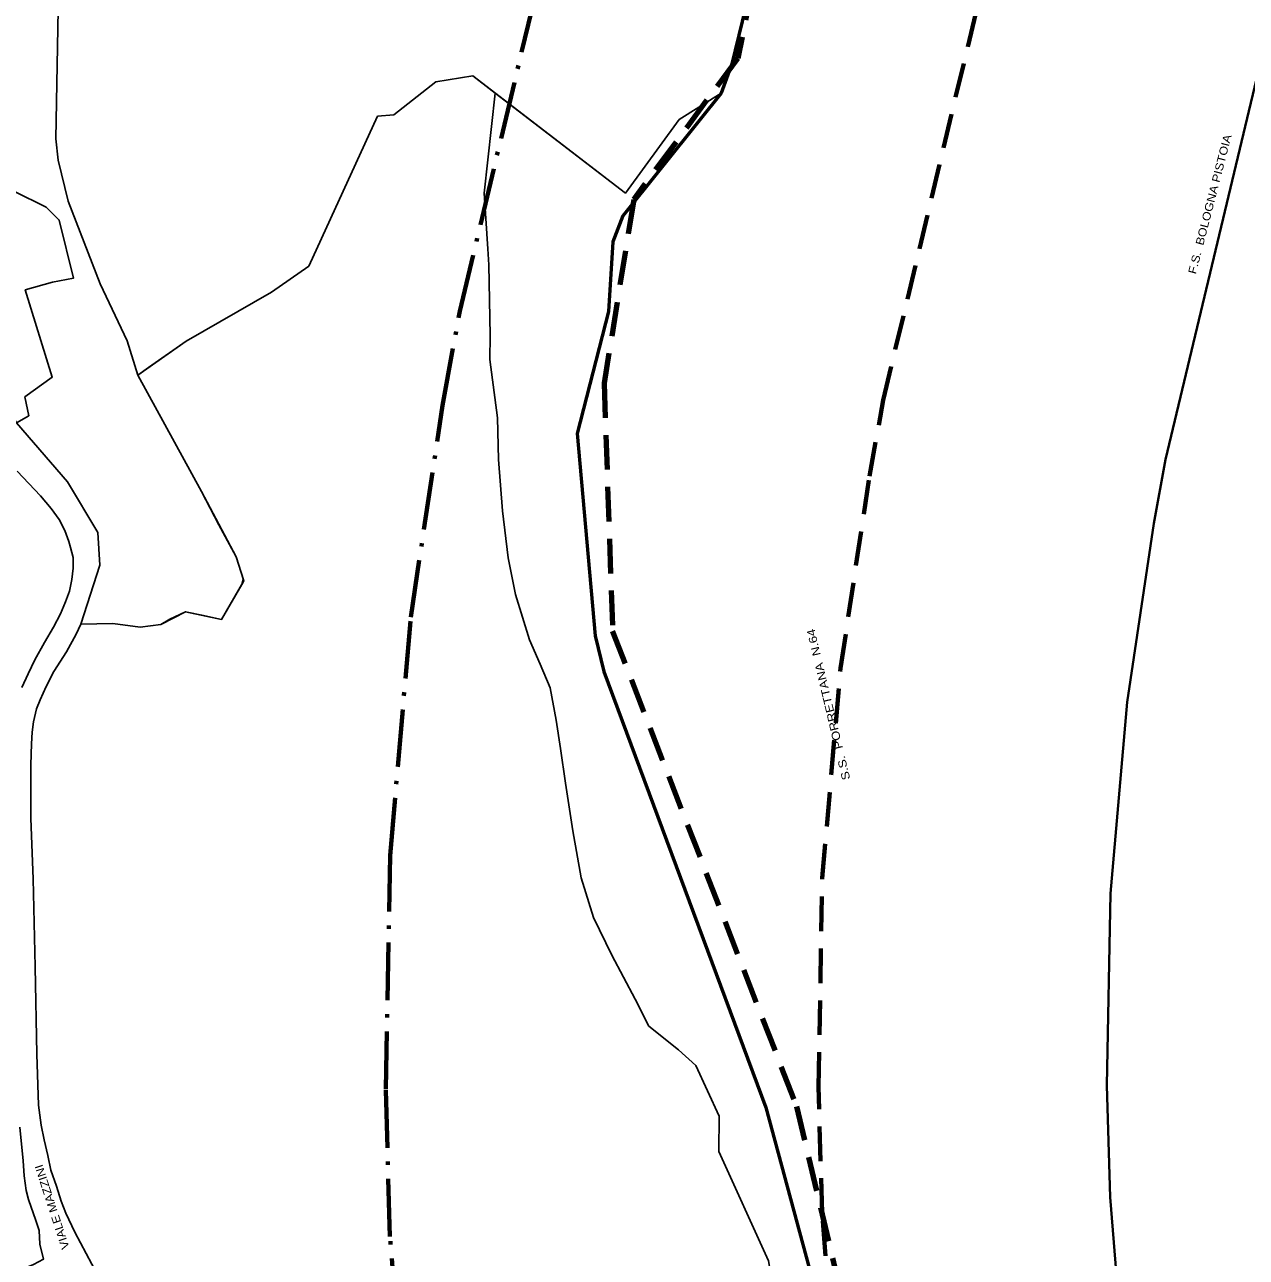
# Model space of a CAD drawing. Extents: x 654952 to 658955, y 890426 to 894481.
# Drawn here: x 657737.9 to 658161.5, y 891916.2 to 892343.7 of the extents above; entities that cross this region are included whole.
import ezdxf

# ---------------------------------------------------------------- set-up
doc = ezdxf.new("R2010")
doc.units = 0
doc.header["$LTSCALE"] = 4
doc.linetypes.add('DOT_DASHED', pattern=[7.7, 5, -1.2, 0.3, -1.2])
doc.linetypes.add('MEDIUM_DASHED', pattern=[4.5, 3, -1.5])
for name, color, linetype, lineweight in [('1', 7, 'Continuous', 25), ('12', 7, 'Continuous', 25), ('26', 7, 'Continuous', 25), ('43', 7, 'Continuous', 25), ('45', 7, 'Continuous', 25), ('55', 7, 'Continuous', 25), ('59', 7, 'Continuous', 53), ('7', 7, 'MEDIUM_DASHED', 100), ('9', 7, 'Continuous', 25)]:
    doc.layers.add(name, color=color, linetype=linetype, lineweight=lineweight)
doc.layers.add('58', color=7, linetype='Continuous')

msp = doc.modelspace()

# ---------------------------------------------------------------- linework, layer by layer
at = {"layer": '1'}
msp.add_lwpolyline([(657736.87, 892113.86), (657739.08, 892118.64), (657741.43, 892123.47), (657744.72, 892129.43), (657747.87, 892134.83), (657750.35, 892139.46), (657752.08, 892143.6), (657753.42, 892147.3), (657754.2, 892151.26), (657754.74, 892155.23), (657754.72, 892158.98), (657753.83, 892162.46), (657753.16, 892164.5), (657751.77, 892168.35), (657749.88, 892172.07), (657747.06, 892175.92), (657743.34, 892180.35), (657735.27, 892188.83)], dxfattribs=at)
at = {"layer": '12'}
for points in [[(657738.45, 891939.43), (657737.71, 891944.48), (657737.33, 891949.76), (657736.18, 891961.41)], [(657742.96, 891925.58), (657741.82, 891928.98), (657739.24, 891936.31), (657738.45, 891939.43)], [(657740.93, 891913.75), (657744.38, 891915.57), (657743.11, 891920.79), (657742.96, 891925.58)]]:
    msp.add_lwpolyline(points, dxfattribs=at)
at = {"layer": '26'}
for points in [[(657897.24, 892285.3), (657901.07, 892319.94), (657893.25, 892325.94), (657880.5, 892323.94), (657865.87, 892312.44), (657860.25, 892311.94), (657836.37, 892259.94), (657823.5, 892250.94), (657793.84, 892234.02), (657777.08, 892222.16)], [(657899.25, 892235.94), (657898.87, 892260.44), (657898.5, 892265.94), (657897.24, 892285.3)], [(657954.34, 891996.44), (657949.62, 892005.77), (657941.44, 892020.98), (657935.11, 892034.15), (657930.83, 892047.81), (657927.92, 892064.19), (657925.38, 892080.66), (657923.63, 892092.72), (657922.23, 892102.53), (657920.15, 892113.8), (657916.61, 892121.94), (657912.97, 892130.41), (657908.08, 892146.1), (657905.52, 892158.87), (657903.61, 892175.14), (657902.18, 892192.88), (657901.88, 892207.4), (657899.22, 892227.63), (657899.25, 892235.94)], [(657777.08, 892222.16), (657799.22, 892181.84), (657805.23, 892170.31), (657811.18, 892159.16), (657813.86, 892150.82), (657806.18, 892137.49)], [(657806.18, 892137.49), (657793.71, 892140.15), (657788.28, 892137.59), (657785.14, 892135.71), (657777.91, 892134.81), (657768.46, 892136), (657757.41, 892135.8)], [(657757.41, 892135.8), (657755.8, 892132.36), (657752.4, 892126.19), (657748.02, 892119.46), (657745.35, 892114.23), (657743.28, 892109.59), (657742.02, 892106.41), (657741, 892101.92), (657740.46, 892098.33), (657740.3, 892094.38), (657740.05, 892087.02), (657739.99, 892082.71), (657740.07, 892068.48), (657740.87, 892047.47), (657741.54, 892017.02), (657742.06, 891986.65), (657742.74, 891969.03)], [(657999.81, 891891.24), (657995.85, 891915.04), (657978.62, 891952.92), (657978.65, 891965.17), (657970.58, 891982.77), (657964.55, 891988.16), (657954.34, 891996.44)], [(657742.74, 891969.03), (657743.62, 891962.05), (657744.69, 891956.96), (657745.87, 891951.55), (657746.96, 891946.43), (657748.9, 891940.97), (657750.54, 891935.67), (657752.22, 891931.58), (657755.25, 891924.94), (657761.15, 891913.87), (657767.14, 891902.38), (657777.05, 891883.31), (657778.51, 891883.96), (657786.61, 891867.17), (657790.42, 891858.02), (657795.5, 891846.02)]]:
    msp.add_lwpolyline(points, dxfattribs=at)
at = {"layer": '43'}
msp.add_line((657813.16, 892149.6), (657813.62, 892151.58), dxfattribs=at)
for points in [[(658040.09, 892492.62), (658015.06, 892461.51), (658007.4, 892428.35), (657983.11, 892330.2), (657979.38, 892319.96), (657964.89, 892310.88), (657946.17, 892285.3), (657893.25, 892325.94), (657880.5, 892323.94), (657865.87, 892312.44), (657860.25, 892311.94), (657836.37, 892259.94), (657823.5, 892250.94), (657793.84, 892234.02), (657780.84, 892224.82)], [(657780.84, 892224.82), (657777.08, 892222.16), (657773.41, 892234.07), (657764.09, 892253.86), (657753.01, 892282.56), (657749.48, 892296.7), (657748.68, 892304.16), (657749.49, 892348.88), (657750.02, 892370.71)], [(657780.84, 892224.82), (657777.08, 892222.16), (657773.41, 892234.07), (657764.09, 892253.86), (657753.01, 892282.56), (657749.48, 892296.7), (657748.68, 892304.16), (657749.49, 892348.88), (657750.02, 892370.71)], [(657703.61, 892356.05), (657701.75, 892325.28), (657700.74, 892305.16), (657700.57, 892296.04), (657702.26, 892286.06), (657704.79, 892275.08), (657714.76, 892245.49), (657723.21, 892226.22), (657735.04, 892205.6), (657752.77, 892185.16), (657763.24, 892167.58), (657763.92, 892156.25), (657757.41, 892135.8), (657768.46, 892136), (657777.91, 892134.81), (657785.14, 892135.71), (657793.71, 892140.15), (657799.95, 892138.82), (657806.18, 892137.49), (657813.16, 892149.6), (657813.62, 892151.58)], [(657979.38, 892319.96), (657964.89, 892310.88), (657946.17, 892285.3), (657901.07, 892319.93), (657897.24, 892285.3)], [(658029.64, 891844.65), (658013.51, 891867.03), (658011.96, 891871.69), (658014.13, 891885.66), (658014.44, 891898.08), (658011.96, 891904.91), (657994.9, 891968.23), (657938.75, 892119.41), (657935.65, 892131.82), (657929.44, 892201.99), (657940.3, 892244.21), (657941.85, 892268.42), (657945.26, 892277.42), (657971.94, 892310.64), (657979.39, 892319.96)], [(657897.24, 892285.3), (657898.5, 892265.94), (657898.87, 892260.44), (657899.25, 892235.94), (657899.22, 892227.63)], [(657899.22, 892227.63), (657901.88, 892207.4), (657902.18, 892192.88), (657903.61, 892175.14), (657905.52, 892158.87), (657908.08, 892146.1), (657912.97, 892130.41)], [(657813.62, 892151.58), (657811.18, 892159.16), (657805.23, 892170.31), (657799.22, 892181.84), (657777.08, 892222.16), (657780.84, 892224.82)], [(657813.62, 892151.58), (657813.86, 892150.82), (657813.16, 892149.6)], [(657912.97, 892130.41), (657916.61, 892121.94), (657920.15, 892113.8), (657922.23, 892102.53), (657923.63, 892092.72), (657925.38, 892080.66), (657927.92, 892064.19), (657930.83, 892047.81), (657935.11, 892034.15), (657941.44, 892020.98), (657949.62, 892005.77), (657954.34, 891996.44), (657964.55, 891988.16), (657970.58, 891982.77), (657978.65, 891965.17), (657978.62, 891952.92), (657995.85, 891915.04), (657999.81, 891891.24)]]:
    msp.add_lwpolyline(points, dxfattribs=at)
at = {"layer": '45', "linetype": 'DOT_DASHED', "lineweight": 70}
msp.add_lwpolyline([(658011.88, 891241.38), (657961.94, 891450.62), (657946.98, 891502.99), (657940.95, 891519.94), (657920.53, 891605.37), (657908.94, 891653.27), (657885.37, 891755.88), (657877.62, 891800.36), (657869.23, 891865.26), (657864.56, 891923.48), (657863.08, 891974.59), (657864.59, 892055.62), (657871.75, 892138.2), (657882.82, 892211.71), (657888.75, 892244.36), (657949.53, 892498.78)], dxfattribs=at)
at = {"layer": '45', "linetype": 'MEDIUM_DASHED', "lineweight": 70}
msp.add_lwpolyline([(658157.77, 891276.21), (658107.08, 891488.64), (658089.9, 891548.82), (658084.95, 891562.68), (658066.38, 891640.44), (658054.95, 891687.7), (658032.46, 891785.55), (658025.97, 891822.86), (658018.45, 891880.89), (658014.38, 891931.66), (658013.11, 891975.37), (658014.47, 892047.73), (658020.79, 892120.53), (658030.81, 892187.14), (658035.6, 892213.52), (658095.39, 892463.77)], dxfattribs=at)
at = {"layer": '45', "lineweight": 40}
msp.add_lwpolyline([(658255.04, 891299.42), (658203.84, 891513.99), (658185.17, 891579.38), (658180.96, 891591.18), (658163.61, 891663.81), (658152.28, 891710.65), (658130.52, 891805.34), (658124.86, 891837.86), (658117.94, 891891.31), (658114.27, 891937.11), (658113.14, 891975.89), (658114.39, 892042.46), (658120.14, 892108.76), (658129.47, 892170.76), (658133.5, 892192.94), (658192.63, 892440.44)], dxfattribs=at)
at = {"layer": '55'}
for points in [[(657813.86, 892150.82), (657811.18, 892159.16), (657799.22, 892181.84), (657777.08, 892222.16), (657773.41, 892234.07), (657764.09, 892253.86), (657753.01, 892282.56), (657749.48, 892296.7), (657748.68, 892304.16), (657749.49, 892348.88), (657750.02, 892370.71)], [(657757.41, 892135.8), (657768.46, 892136), (657777.91, 892134.81), (657785.14, 892135.71), (657788.28, 892137.59), (657793.71, 892140.15), (657806.18, 892137.49), (657813.86, 892150.82)], [(657742.74, 891969.03), (657742.06, 891986.65), (657741.54, 892017.02), (657740.87, 892047.47), (657740.07, 892068.48), (657739.99, 892082.71), (657740.05, 892087.02), (657740.3, 892094.38), (657740.46, 892098.33), (657741, 892101.92), (657742.02, 892106.41), (657743.28, 892109.59), (657745.35, 892114.23), (657748.02, 892119.46), (657752.4, 892126.19), (657755.8, 892132.36), (657757.41, 892135.8)], [(657750.54, 891935.67), (657748.9, 891940.97), (657746.96, 891946.43), (657745.87, 891951.55), (657744.69, 891956.96), (657743.62, 891962.05), (657742.74, 891969.03)], [(657737.33, 891949.76), (657737.71, 891944.48), (657738.45, 891939.43), (657739.24, 891936.31), (657741.82, 891928.98), (657742.96, 891925.58), (657743.11, 891920.79), (657744.38, 891915.57), (657740.93, 891913.75), (657700.14, 891897.46)], [(657767.14, 891902.38), (657761.15, 891913.87), (657755.25, 891924.94), (657752.22, 891931.58), (657750.54, 891935.67)]]:
    msp.add_lwpolyline(points, dxfattribs=at)
at = {"layer": '59'}
msp.add_lwpolyline([(658015.06, 892461.51), (657983.11, 892330.2), (657979.39, 892319.96), (657971.94, 892310.64), (657945.26, 892277.42), (657941.85, 892268.42), (657940.3, 892244.21), (657929.44, 892201.99), (657935.65, 892131.82), (657938.75, 892119.41), (657994.9, 891968.23), (658011.96, 891904.91), (658014.44, 891898.08), (658014.13, 891885.66), (658011.96, 891871.69), (658013.51, 891867.03), (658032.75, 891840.34), (658069.36, 891782.29), (658089.83, 891749.07), (658127.68, 891653.47), (658151.87, 891546.37), (658165.52, 891469.7)], dxfattribs=at)
at = {"layer": '7'}
msp.add_lwpolyline([(658011.87, 892462.81), (657985.13, 892331.98), (657949.09, 892283.08), (657938.8, 892219.4), (657941.76, 892133.42), (658005.57, 891968.55), (658020.45, 891905.51), (658017.23, 891880.43), (658094.78, 891763.01), (658139.37, 891654.66), (658174.09, 891483.56)], dxfattribs=at)
at = {"layer": '9'}
msp.add_lwpolyline([(657700.56, 892300.88), (657711.87, 892299.94), (657716.63, 892298.94), (657723.37, 892295.94), (657729.5, 892290.94), (657734.13, 892285.94), (657745.37, 892280.44), (657749.87, 892275.94), (657754.78, 892255.81), (657747.5, 892254.44), (657738.08, 892251.71), (657747.43, 892221.45), (657737.96, 892214.62), (657739.29, 892208.08), (657735.04, 892205.6), (657723.21, 892226.22), (657714.76, 892245.49), (657704.79, 892275.08), (657700.57, 892296.04)], dxfattribs=at)

# ---------------------------------------------------------------- texts
at = {"layer": '58'}
for s, height, rotation, width, p in [('F.S.  BOLOGNA PISTOIA', 2.8, 75.537, 1.15, (658143.97, 892257.03)), ('S.S.  PORRETTANA  N.64', 2.803, 103.378, 1.2, (658024.17, 892082.12)), ('VIALE MAZZINI', 2.802, 108.031, 1.15, (657753.47, 891919.58))]:
    msp.add_text(s, height=height, rotation=rotation, dxfattribs=dict(at, width=width)).set_placement(p)

doc.saveas('drawing.dxf')
